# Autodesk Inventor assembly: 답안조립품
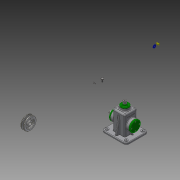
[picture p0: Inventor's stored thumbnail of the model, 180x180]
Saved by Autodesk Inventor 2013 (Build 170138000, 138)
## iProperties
Created: 2016-01
Part Number: 답안조립품
Document SubType Name: Assembly
Designer: Administrator
Author: Administrator
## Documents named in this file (19)
- C:\Users\Administrator\Desktop\460127V1003\답안조립품.iam
- C:\Users\Administrator\Desktop\460127V1003\1.본체.ipt
- C:\Users\Administrator\Desktop\460127V1003\V-벨트풀리.ipt
- C:\Users\Administrator\Desktop\460127V1003\고정핀.ipt
- C:\Users\Administrator\Desktop\460127V1003\뒤커버.ipt
- C:\Users\Administrator\Desktop\460127V1003\링크.ipt
- C:\Users\Administrator\Desktop\460127V1003\멈춤링 6 x 5.ipt
- C:\Users\Administrator\Desktop\460127V1003\멈춤링 15 x 1.ipt
- C:\Users\Administrator\Desktop\460127V1003\베어링 15 x 35 x 11.ipt
- C:\Users\Administrator\Desktop\460127V1003\볼트 M3 x 8.ipt
- C:\Users\Administrator\Desktop\460127V1003\볼트 M4 x 10.ipt
- C:\Users\Administrator\Desktop\460127V1003\볼트 M6 x 12.ipt
- C:\Users\Administrator\Desktop\460127V1003\상부부시.ipt
- C:\Users\Administrator\Desktop\460127V1003\슬라이드바.ipt
- C:\Users\Administrator\Desktop\460127V1003\앞커버.ipt
- C:\Users\Administrator\Desktop\460127V1003\오일실 15 25 7.ipt
- C:\Users\Administrator\Desktop\460127V1003\와셔.ipt
- C:\Users\Administrator\Desktop\460127V1003\키 5 x 5 x 14.ipt
- C:\Users\Administrator\Desktop\460127V1003\편심축.ipt
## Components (13 placed, 6 different names)
1. 1.본체:1
2. V-벨트풀리:1
3. 고정핀:1
4. ISO 4762 M3 x 8:1
5. ISO 4018 M6 x 12:1
6. ISO 4762 M4 x 10:1
7. ISO 4762 M4 x 10:3
8. ISO 4762 M4 x 10:4
9. ISO 4762 M4 x 10:5
10. ISO 4762 M4 x 10:2
11. ISO 4762 M4 x 10:6
12. ISO 4762 M4 x 10:7
13. ISO 4762 M4 x 10:8
